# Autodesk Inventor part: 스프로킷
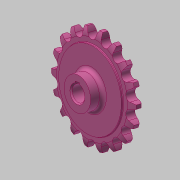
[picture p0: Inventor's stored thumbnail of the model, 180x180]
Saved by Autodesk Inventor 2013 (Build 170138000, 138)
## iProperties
Created: 2016-03
Part Number: 스프로킷
Material: 강철, 탄소
Document SubType Name: Modeling
Designer: mduedu
Density: 7.87 g/cm^3
Mass: 301.818 g
Surface Area: 124.882 cm^2
Volume: 38.3505 cm^3
Author: mduedu
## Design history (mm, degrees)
sketch "스케치1"
  geometry: L1 (0, 5)-(29.5, 5); L2 (29.5, 5)-(29.5, 4.1); L3 (30, 3.6)-(33.625, 3.6); L4 (40, 2)-(40, 0); L5 (40, 0)-(0, 0); L6 (0, 0)-(0, 5); L7 (0, -5)-(29.5, -5); L8 (29.5, -5)-(29.5, -4.1); L9 (30, -3.6)-(33.625, -3.6); L10 (40, -2)-(40, 0); L11 (0, 0)-(0, -5); A1 r 13.5 centre (33.625, -9.9) between (40, 2) and (33.625, 3.6); A2 r 13.5 centre (33.625, 9.9) between (33.625, -3.6) and (40, -2); A3 r 0.5 centre (30, 4.1) between (29.5, 4.1) and (30, 3.6); A4 r 0.5 centre (30, -4.1) between (30, -3.6) and (29.5, -4.1); 2 further points
  constraints: 22 end point, 8 point on circle, 6 symmetric about line, 5 tangent, 4 centre point, 4 parallel, 4 point on line, 1 equal radius, 1 horizontal, 1 perpendicular, 1 other
  dimensions: "d0" = 80 diameter of L4 L6; "d2" = 59 diameter of L2 L6; "d3" = 1.6 vertical distance of L4.start L3.end; "d4" = 3.6 distance from line of L4.end L3; "d5" = 5 distance between parallel lines of L5 L1; "d6" = 13.5 radius of A1; "d15" = 0.5 radius of A3
revolve "회전1" sketch "스케치1" stored, may be unused: angle "d7" = 90 deg
sketch "스케치2" dims "d8" = 65.2, "d11" = 80
  geometry: L1 (0, 0)-(0, 32.6); A1 r 36.57 centre (0, 0) between (-16.231, 32.771) and (0, 36.57); A2 r 3.97 centre (0, 36.57) between (-3.866, 35.665) and (0, 32.6); A3 r 12.7 centre (-16.231, 32.771) between (-3.866, 35.665) and (-5.534, 39.615); A4 r 12.7 centre (16.231, 32.771) between (5.534, 39.615) and (3.866, 35.665); A5 r 3.97 centre (0, 36.57) between (0, 32.6) and (3.866, 35.665); A6 r 40 centre (0, 0) between (5.534, 39.615) and (-5.534, 39.615); 2 further points
  constraints: 12 point on circle, 6 centre point, 4 coincident, 3 symmetric about line, 2 end point, 1 point on line, 1 tangent, 1 vertical, 1 vertical alignment, 7 other
  dimensions: "d10" = 73.14 diameter of A1; "d12" = 12.7 radius of A3
extrude "돌출1" cut sketch "스케치2" stored distance "d13" = 10; taper "d14" = 0 deg
sketch "스케치3"
  geometry: C1 r 12.5 at (0, 0); 1 further point
  constraints: 1 centre point, 1 coincident
  dimensions: "d19" = 25 diameter of C1
extrude "돌출2" join sketch "스케치3" distance "d20" = 10; taper "d21" = 0 deg
fillet "모깎기1" dims "d22" = 3
sketch "스케치4"
  geometry: L1 (-2, 0)-(2, 0); L2 (2, 0)-(2, 7.8); L3 (2, 7.8)-(-2, 7.8); L4 (-2, 7.8)-(-2, 0); C1 r 6 at (0, 0); 2 further points
  constraints: 8 end point, 2 coincident, 2 parallel, 1 centre point, 1 horizontal, 1 midpoint, 1 perpendicular
  dimensions: "d23" = 12 diameter of C1; "d25" = 4 distance of L2.end L3.end; "d26" = 7.8 distance of L1.end L2.end
extrude "돌출3" cut sketch "스케치4" stored distance "d27" = 8; taper "d28" = 0 deg
chamfer "모따기2" distance "d42" = 1; stored, may be unused: second distance "d43" = 2, angle "d44" = 45 deg
node "솔리드1"
pattern_circular "원형 패턴1" dims angle "d17" = 360 deg
